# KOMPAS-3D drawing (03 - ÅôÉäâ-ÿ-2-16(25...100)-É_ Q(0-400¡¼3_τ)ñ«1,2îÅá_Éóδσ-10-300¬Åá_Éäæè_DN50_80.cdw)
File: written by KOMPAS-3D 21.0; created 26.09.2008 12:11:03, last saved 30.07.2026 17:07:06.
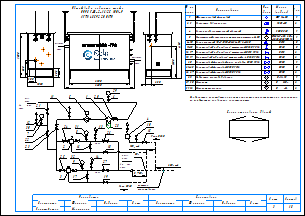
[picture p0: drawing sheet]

Sheets 1-2: A3, landscape

Document properties: Наименование: Макро:21; Автор: RaskoAdmin; Форматы листов документа: 2xA3; Полное имя файла: \\ur38nt01\Departments\КТО\КБ ПУРДГ\Заявки\Прайс-лист на типовые шкафы ГРПШ\ПУРДГ_стандарт_30_04_2026\ПУРДГ с РДСК\ПУРДГ-Ш-2-16(25...100)-Р_ Q(0-400нм3_ч)до1,2МПа_Рвых-10-300кПа_РДСК_DN50_80.cdw

Title block, sheet 1: Наименование: Пункт учета газа / ПУГ-Ш-400-Р / ЛГТИ.485922.001ТУ; designation: ЛГТИ.03.4411141; sheet number: 1; Количество листов документа: 2; organisation: ООО "ЭЛЬСТЕР Газэлектроника"; Форматы листов документа: A3; stored path: C:\Рабочие документы\Компас\ПУГ\Схема.cdw; Разработал: Устинов; Проверил: Кошкин; Утвердил: Кошкин
Title block, sheet 2: sheet number: 2; stored path: D:\Рабочие документы\Заявки\ПУРДГ\ПУРДГ-ШУЭО-2-100-Р 4411220.cdw; designation, second copy: ЛГТИ.03.4411141-

Views: Вид 1, Вид 2
Referenced files: wcvoit.frw
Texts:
  Normal
  № на
  схеме
  Усл.
  обозн.
  Марка
  (модель)
  Кол.
  Фильтр газовый фланцевый
  ФГ 16-50
  Регулятор давления газа
  РДСК-50
  Клапан предохранительный сбросной
  КПС DN20
  Измерительный комплекс с ротационным счетчиком Ду50
  СГ-ЭК-Р-(0,2...2,0)-
  Кран кнопочный VE-РАСКО-НЗ-1,6-G1/2-М20
  DN15
  Кран шаровой "под приварку" штуцерный DN20 PN16
  DN20
  Кран шаровой "под приварку" штуцерный DN15 PN16
  Кран шаровой "под приварку" штуцерный п/п DN20 PN16
  Кран шаровой фланцевый с мех. приводом DN50 PN16
  Кран шаровой фланцевый DN50 PN16
  Кран шаровой фланцевый DN80 PN16
  DN50
  DN80
  Индикатор перепада давления
  Манометр
  Манометр-напоромер
  Delta 15
  0...     МПа
  0...     кПа
  Общий вид и габариты шкафа
  ПУРДГ-Ш-2-16(25...100)-Р
  Выход газа
  Вход газа
  logo-rasko-ge.png
  DN 1
  местное
  сопротивление
  Римп DN20
  Выход
  газа
  Р=     кПа
  Вход
  Р=       МПа
  PDI
  Схема открывания дверей
  Предприятие изготовитель может заменять комплектующие на аналогичные,
  не ухудшающие заявленных характеристик.
  Должность
  Конструктор
  Фамилия
  Подпись
  Дата
  Согласовано
  Максимкин
  Лист
  Листов
  POLYLINE_STYLE_0.18_RGB_0_0_0
  POLYLINE_STYLE_0.50_RGB_0_0_0
  POLYLINE_STYLE_0.34_RGB_0_0_0
  PHANTOM_RGB_0_0_0_SC_1_THICK_0.18
  K5LT_THIN_RGB_0_0_0_THICK_0.18
  K5LT32769_RGB_0_0_0_THICK_0.18
  K5LT12_RGB_0_0_0_SC_1_THICK_0.18
  K5LT_DASHED_RGB_0_0_0_SC_1_THICK_0.18
  ACISOTGL_RGB_0_0_0_SC_0.8_THICK_0.25
  CONTINUOUS_RGB_0_127_31_THICK_0.3
  CONTINUOUS_RGB_0_0_255_THICK_0.35
  CONTINUOUS_RGB_255_0_0_THICK_0.35
  POLYLINE_STYLE_0.25_RGB_0_0_0
  CONTINUOUS_RGB_0_0_0_THICK_0.5
  POLYLINE_STYLE_0.35_RGB_0_0_255
  CONTINUOUS_RGB_0_0_0_THICK_0.4
  CONTINUOUS_RGB_0_0_0_THICK_0.35
  НЕВИДИМАЯ_RGB_0_0_0_SC_0.3_THICK_0.25
  СONTINUOUS_RGB_0_0_0_THICK_0.25
  ОСЕВАЯ2_RGB_248_153_30_SC_0.3_THICK_0.25
  Без оформления
Dimensions and other numbers on the sheet: 1; 2, 3; 2; 4; 5; 6-10; 11-15; 16, 17; 18, 19; 20; 21-25; 26, 27; 28; 29, 30; 31, 32; 1500; 250; 300; 1050; 550; 305; 2300; 4130; 2000; 2600; 5,,,7DN 1; 7; 30; 12; 21; 22; 23; 11; 6; 29; 24; 31; 8; 16; 13; 26; 18; 10; 15; 25; 32; 9; 3; 17; 14; 27; 19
